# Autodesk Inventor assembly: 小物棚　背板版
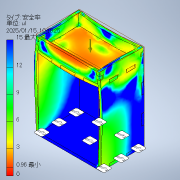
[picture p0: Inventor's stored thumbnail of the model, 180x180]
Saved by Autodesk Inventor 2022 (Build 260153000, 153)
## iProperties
Created: 2024-12
Part Number: 小物棚　背板版
Document SubType Name: Assembly
Designer: shimizu
Mass: 30.95 g
Surface Area: 349.8 cm^2
Volume: 38.6875 cm^3
Density: 0.8 g/cm^3
Author: shimizu
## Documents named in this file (6)
- C:\Users\shimizu\Documents\卒論2024\3DCAD\小物棚 - 背板版\組立図\小物棚　背板版.iam
- C:\Users\shimizu\Documents\卒論2024\3DCAD\小物棚 - 背板版\部品図\底板.ipt
- C:\Users\shimizu\Documents\卒論2024\3DCAD\小物棚 - 背板版\部品図\側板.ipt
- C:\Users\shimizu\Documents\卒論2024\3DCAD\小物棚 - 背板版\部品図\天板.ipt
- C:\Users\shimizu\Documents\卒論2024\3DCAD\小物棚 - 背板版\部品図\側板②.ipt
- C:\Users\shimizu\Documents\卒論2024\3DCAD\小物棚 - 背板版\部品図\背板.ipt
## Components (6 placed, 5 different names)
1. 底板:1 — メイト:1, フラッシュ:1, フラッシュ:2, メイト:2, フラッシュ:3, フラッシュ:4, メイト:6
2. 側板:1 — メイト:2, フラッシュ:3, フラッシュ:4, フラッシュ:5, メイト:3
3. 側板:2 — メイト:1, フラッシュ:1, フラッシュ:2, フラッシュ:6, フラッシュ:7, フラッシュ:8, フラッシュ:9
4. 天板:1 — フラッシュ:5, フラッシュ:6, メイト:3, メイト:4, メイト:5
5. 側板②:1 — メイト:4, フラッシュ:7, フラッシュ:8
6. 背板:1 — メイト:5, メイト:6, フラッシュ:9
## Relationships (15: Flush 9, Mate 6)
- メイト:1 [Mate]: 底板:1 ↔ 側板:2
- フラッシュ:1 [Flush]: 底板:1 ↔ 側板:2
- フラッシュ:2 [Flush]: 底板:1 ↔ 側板:2
- メイト:2 [Mate]: 底板:1 ↔ 側板:1
- フラッシュ:3 [Flush]: 底板:1 ↔ 側板:1
- フラッシュ:4 [Flush]: 底板:1 ↔ 側板:1
- フラッシュ:5 [Flush]: 側板:1 ↔ 天板:1
- フラッシュ:6 [Flush]: 側板:2 ↔ 天板:1
- メイト:3 [Mate]: 側板:1 ↔ 天板:1
- メイト:4 [Mate]: 天板:1 ↔ 側板②:1
- フラッシュ:7 [Flush]: 側板:2 ↔ 側板②:1
- フラッシュ:8 [Flush]: 側板:2 ↔ 側板②:1
- メイト:5 [Mate]: 天板:1 ↔ 背板:1
- メイト:6 [Mate]: 底板:1 ↔ 背板:1
- フラッシュ:9 [Flush]: 側板:2 ↔ 背板:1
## Named parameters: sa_0 = 220000 mm
